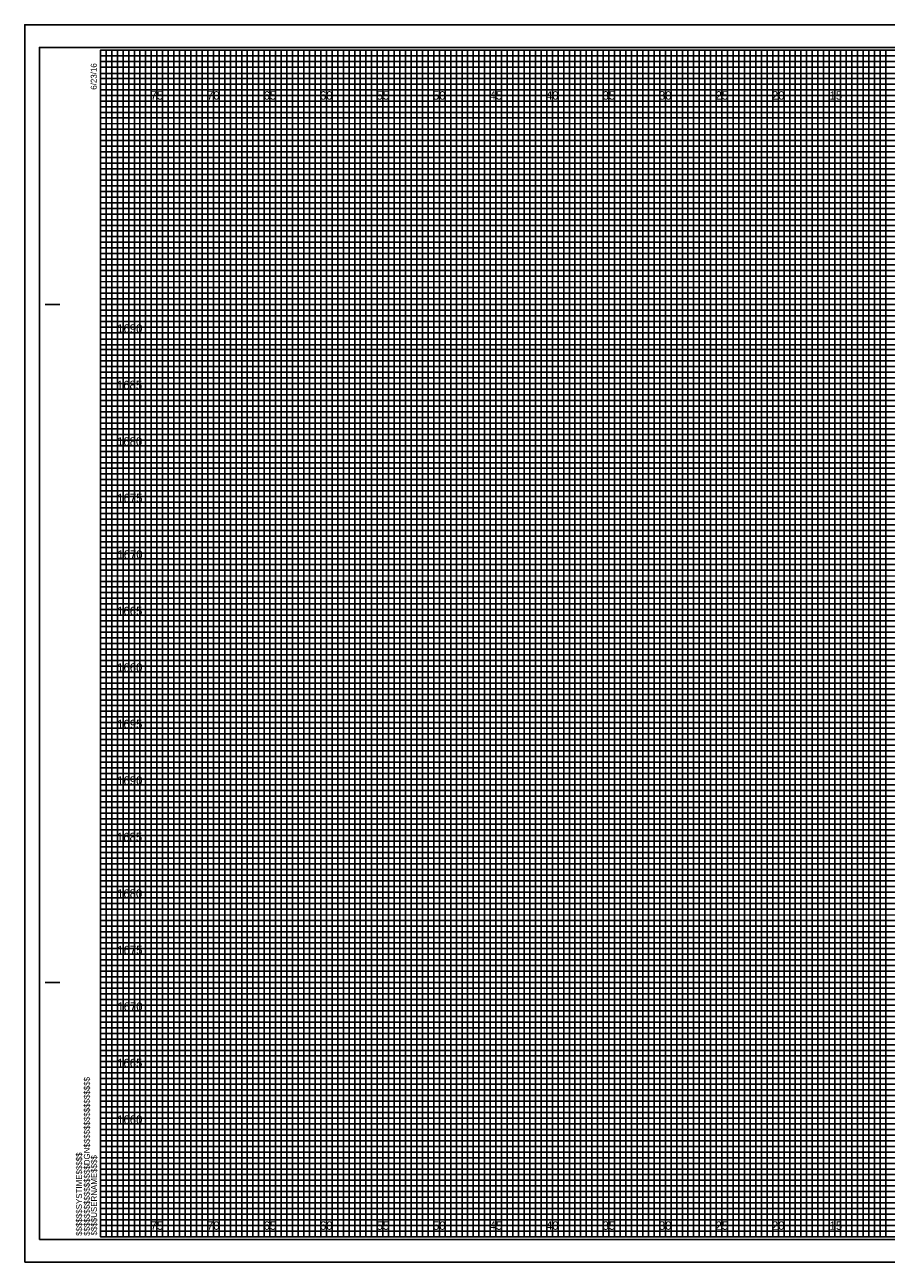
# Model space of a CAD drawing. Extents: x -7 to 162, y -2 to 327.
# Drawn here: x -6.7 to 69.5, y 107.7 to 217.2 of the extents above; entities that cross this region are included whole.
import ezdxf

# ---------------------------------------------------------------- set-up
doc = ezdxf.new("R2010")
doc.units = 0
for name, color, linetype in [('Raster_Level_0', 7, 'Continuous'), ('Scratch_Level_3', 7, 'Continuous'), ('Sheet Cross Section CELL', 7, 'Continuous'), ('Sheet Cross Section Grid Major CELL', 7, 'Continuous'), ('Sheet Cross Section Grid Middle CELL', 7, 'Continuous'), ('Sheet Cross Section Grid Minor 1 CELL', 7, 'Continuous'), ('Sheet Cross Section Grid Minor 2 CELL', 7, 'Continuous'), ('Sheet Cutting Line CELL', 7, 'Continuous'), ('Sheet DOT Grid CELL', 7, 'Continuous'), ('Sheet Plot Border Inside CELL', 7, 'Continuous'), ('Sheet Plot Border Outside CELL', 7, 'Continuous')]:
    doc.layers.add(name, color=color, linetype=linetype)

msp = doc.modelspace()

# ---------------------------------------------------------------- linework, layer by layer
at = {"layer": 'Sheet Cross Section CELL'}
for p, q in [((-4.9, 192.5), (-3.65, 192.5)), ((-4.85, 192.5), (-3.6, 192.5)), ((-4.9, 132.5), (-3.65, 132.5)), ((-4.85, 132.5), (-3.6, 132.5)), ((0, 110), (0, 110)), ((0, 110), (0, 110)), ((0, 110), (0, 110)), ((0, 110), (0, 110)), ((0, 110), (0, 110)), ((0, 110), (0, 110)), ((0, 110), (0, 110))]:
    msp.add_line(p, q, dxfattribs=at)
msp.add_lwpolyline([(160, 215), (0, 215), (0, 110), (160, 110)], close=True, dxfattribs=at)
at = {"layer": 'Sheet Cross Section Grid Major CELL'}
for p, q in [((5, 215), (0, 215)), ((5, 110), (5, 215)), ((15, 215), (10, 215)), ((10, 215), (10, 110)), ((15, 110), (15, 215)), ((25, 215), (20, 215)), ((20, 215), (20, 110)), ((25, 110), (25, 215)), ((35, 215), (30, 215)), ((30, 215), (30, 110)), ((35, 110), (35, 215)), ((45, 215), (40, 215)), ((40, 215), (40, 110)), ((45, 110), (45, 215)), ((55, 215), (50, 215)), ((50, 215), (50, 110)), ((55, 110), (55, 215)), ((65, 215), (60, 215)), ((60, 215), (60, 110)), ((65, 110), (65, 215)), ((10, 110), (5, 110)), ((20, 110), (15, 110)), ((30, 110), (25, 110)), ((40, 110), (35, 110)), ((50, 110), (45, 110)), ((60, 110), (55, 110)), ((70, 110), (65, 110))]:
    msp.add_line(p, q, dxfattribs=at)
for points in [[(0, 210), (160, 210), (160, 205), (0, 205)], [(0, 200), (160, 200), (160, 195), (0, 195)], [(0, 190), (160, 190), (160, 185), (0, 185)], [(0, 180), (160, 180), (160, 175), (0, 175)], [(0, 170), (160, 170), (160, 165), (0, 165)], [(0, 160), (160, 160), (160, 155), (0, 155)], [(0, 150), (160, 150), (160, 145), (0, 145)], [(0, 140), (160, 140), (160, 135), (0, 135)], [(0, 130), (160, 130), (160, 125), (0, 125)], [(0, 120), (160, 120), (160, 115), (0, 115)]]:
    msp.add_lwpolyline(points, dxfattribs=at)
at = {"layer": 'Sheet Cross Section Grid Middle CELL'}
for points in [[(0, 215), (2.5, 215), (2.5, 110), (7.5, 110), (7.5, 215), (12.5, 215), (12.5, 110), (17.5, 110), (17.5, 215), (22.5, 215), (22.5, 110), (27.5, 110), (27.5, 215), (32.5, 215), (32.5, 110), (37.5, 110), (37.5, 215), (42.5, 215), (42.5, 110), (47.5, 110), (47.5, 215), (52.5, 215), (52.5, 110), (57.5, 110), (57.5, 215), (62.5, 215), (62.5, 110), (67.5, 110), (67.5, 215), (72.5, 215)], [(0, 212.5), (137.5, 212.5)], [(0, 202.5), (160, 202.5), (160, 207.5), (0, 207.5)], [(0, 192.5), (160, 192.5), (160, 197.5), (0, 197.5)], [(0, 182.5), (160, 182.5), (160, 187.5), (0, 187.5)], [(0, 172.5), (160, 172.5), (160, 177.5), (0, 177.5)], [(0, 162.5), (160, 162.5), (160, 167.5), (0, 167.5)], [(0, 152.5), (160, 152.5), (160, 157.5), (0, 157.5)], [(0, 142.5), (160, 142.5), (160, 147.5), (0, 147.5)], [(0, 132.5), (160, 132.5), (160, 137.5), (0, 137.5)], [(0, 122.5), (160, 122.5), (160, 127.5), (0, 127.5)], [(0, 112.5), (160, 112.5), (160, 117.5), (0, 117.5)]]:
    msp.add_lwpolyline(points, dxfattribs=at)
at = {"layer": 'Sheet Cross Section Grid Minor 1 CELL'}
for p, q in [((0, 214.5), (130, 214.5)), ((130, 213.99), (0, 213.99)), ((0, 213.99), (0, 213.5)), ((0, 213.5), (130, 213.5)), ((130, 212.94), (0, 212.94)), ((0, 212.94), (0, 212)), ((0, 212), (160, 212))]:
    msp.add_line(p, q, dxfattribs=at)
for points in [[(0, 211.5), (135, 211.5), (160, 211.5), (160, 211), (0, 211)], [(0, 210.5), (160, 210.5), (160, 209.5), (0, 209.5)], [(0, 209), (160, 209), (160, 208.5), (0, 208.49)], [(0, 208), (160, 208), (160, 207), (0, 207)], [(0, 206.5), (160, 206.5), (160, 206), (0, 206)], [(0, 205.5), (160, 205.5), (160, 204.5), (0, 204.5)], [(0, 204), (160, 204), (160, 203.5), (0, 203.5)], [(0, 203), (160, 203), (160, 202), (0, 202)], [(0, 201.5), (160, 201.5), (160, 201), (0, 201)], [(0, 200.5), (160, 200.5), (160, 199.5), (0, 199.5)], [(0, 199), (160, 199), (160, 198.5), (0, 198.5)], [(0, 198), (160, 198), (160, 196.97), (160, 196.5), (160, 196), (0, 196)], [(0, 197), (160, 197), (160, 196.5), (0, 196.5)], [(0, 195.5), (160, 195.5), (160, 194.5), (0, 194.52)], [(0, 194.52), (160, 194.5), (160, 194), (0, 194)], [(0, 193.5), (160, 193.5), (160, 193), (0, 193)], [(0, 192), (160, 192), (160, 191.5), (0, 191.5)], [(0, 191), (160, 191), (160, 190.5), (0, 190.5)], [(-0.04, 189.44), (160, 189.44), (160, 188.94), (-0.04, 188.94)], [(0, 188.5), (160, 188.5), (160, 188), (0, 188)], [(0, 187), (160, 187), (160, 186.5), (0, 186.5)], [(0, 186), (160, 186), (160, 185.5), (0, 185.5)], [(0, 184.5), (160, 184.5), (160, 184), (0, 184)], [(0, 183.5), (160, 183.5), (160, 183), (0, 183)], [(0, 182), (160, 182), (160, 181.5), (0, 181.5)], [(0, 181), (160, 181), (160, 180.5), (0, 180.5)], [(0, 179.5), (160, 179.5), (160, 178.99), (0, 179)], [(0, 178.5), (160, 178.5), (160, 178), (0, 178)], [(0, 177), (160, 177), (160, 176.5), (0, 176.5)], [(0, 176), (160, 176), (160, 175.5), (0, 175.5)], [(0, 174.5), (160, 174.5), (160, 174), (0, 174)], [(0, 173.5), (160, 173.5), (160, 173), (0, 173)], [(0, 172), (160, 172), (160, 171.5), (0, 171.5)], [(0, 171), (160, 171), (160, 170.5), (0, 170.5)], [(0, 169.5), (160, 169.5), (160, 169), (0, 169)], [(0, 168.5), (160.03, 168.46), (160, 168), (0, 168)], [(0, 167), (160, 167), (160, 166.5), (0, 166.5)], [(0, 166), (160, 166), (160, 165.5), (0, 165.5)], [(0, 164.5), (160, 164.5), (160, 164), (0, 164)], [(0, 163.5), (160, 163.5), (160, 163), (0, 163)], [(0, 162), (160, 162), (160, 161.5), (0, 161.5)], [(0, 161), (160, 161), (160, 160.5), (0, 160.5)], [(0, 159.5), (160, 159.5), (160, 159), (0, 159)], [(0, 158.5), (160, 158.5), (160, 158), (0, 158)], [(0, 157), (160, 157), (160, 156.5), (0, 156.5)], [(0, 156), (160, 156), (160, 155.5), (0, 155.5)], [(0, 154.5), (160, 154.5), (160, 154), (0, 154)], [(0, 153.5), (160, 153.5), (160, 153), (0, 153)], [(0, 152), (160, 152), (160, 151.5), (0, 151.5)], [(0, 151), (160, 151), (160, 150.5), (0, 150.5)], [(0, 149.5), (160, 149.5), (160, 148.99), (0, 149)], [(0, 148.5), (160, 148.5), (160, 148), (0, 148)], [(0, 147), (160, 147), (160, 146.5), (0, 146.5)], [(0, 146), (160, 146), (160, 145.5), (0, 145.5)], [(0, 144.5), (160, 144.5), (160, 144), (0, 144)], [(0, 143.5), (160, 143.5), (160, 143), (0, 143)], [(0, 142), (160, 142), (160, 141.5), (0, 141.5)], [(0, 141), (160, 141), (160, 140.5), (0, 140.5)], [(0, 139.5), (160, 139.5), (160, 139), (0, 139)], [(0, 138.5), (160.03, 138.46), (160, 138), (0, 138)], [(0, 137), (160, 137), (160, 136.5), (0, 136.5)], [(0, 136), (160, 136), (160, 135.5), (0, 135.5)], [(0, 134.5), (160, 134.5), (160, 134), (0, 134)], [(0, 133.5), (160, 133.5), (160, 133), (0, 133)], [(0, 132), (160, 132), (160, 131.5), (0, 131.5)], [(0, 131), (160, 131), (160, 130.5), (0, 130.5)], [(0, 129.5), (160, 129.5), (160, 129), (0, 129)], [(0, 128.5), (160, 128.5), (160, 128), (0, 128)], [(0, 127), (160, 127), (160, 126.5), (0, 126.5)], [(0, 126), (160, 126), (160, 125.5), (0, 125.5)], [(0, 124.5), (160, 124.5), (160, 124), (0, 124)], [(0, 123.5), (160, 123.5), (160, 123), (0, 123)], [(0, 122), (160, 122), (160, 121.5), (0, 121.5)], [(0, 121), (160, 121), (160, 120.5), (0, 120.5)], [(0, 119.5), (160, 119.5), (160, 119), (0, 119)], [(0, 118.5), (160, 118.5), (160, 118), (0, 118)], [(0, 117), (160, 117), (160, 116.5), (0, 116.5)], [(0, 116), (160, 116), (160, 115.5), (0, 115.5)], [(0, 114.5), (160, 114.5), (160, 114), (0, 114)], [(0, 113.5), (160, 113.5), (160, 113), (0, 113)], [(0, 112), (160, 112), (160, 111.5), (0, 111.5)], [(0, 111), (160, 111), (160, 110.5), (0, 110.5)]]:
    msp.add_lwpolyline(points, dxfattribs=at)
at = {"layer": 'Sheet Cross Section Grid Minor 2 CELL'}
for points in [[(0, 110), (0.5, 110), (0.5, 215), (1, 215), (1, 110)], [(1, 110), (1.5, 110), (1.5, 215), (2, 215), (2, 110)], [(2.5, 110), (3, 110), (3, 215), (3.5, 215), (3.5, 110)], [(3.5, 110), (4, 110), (4, 215), (4.5, 215), (4.5, 110)], [(5, 110), (5.5, 110), (5.5, 215), (6, 215), (6, 110)], [(6, 110), (6.5, 110), (6.5, 215), (7, 215), (7, 110)], [(7.5, 110), (8, 110), (8, 215), (8.5, 215), (8.5, 110)], [(8.5, 110), (9, 110), (9, 215), (9.5, 215), (9.5, 110)], [(10, 110), (10.5, 110), (10.5, 215), (11, 215), (11, 110)], [(11, 110), (11.5, 110), (11.5, 215), (12, 215), (12, 110)], [(12.5, 110), (13, 110), (13, 215), (13.5, 215), (13.5, 110)], [(13.5, 110), (14, 110), (14, 215), (14.5, 215), (14.5, 110)], [(15, 110), (15.5, 110), (15.5, 215), (16, 215), (16, 110)], [(16, 110), (16.5, 110), (16.5, 215), (17, 215), (17, 110)], [(17.5, 110), (18, 110), (18, 215), (18.5, 215), (18.5, 110)], [(18.5, 110), (19, 110), (19, 215), (19.5, 215), (19.5, 110)], [(20, 110), (20.5, 110), (20.5, 215), (21, 215), (21, 110)], [(21, 110), (21.5, 110), (21.5, 215), (22, 215), (22, 110)], [(22.5, 110), (23, 110), (23, 215), (23.5, 215), (23.5, 110)], [(23.5, 110), (24, 110), (24, 215), (24.5, 215), (24.5, 110)], [(25, 110), (25.5, 110), (25.5, 215), (26, 215), (26, 110)], [(26, 110), (26.5, 110), (26.5, 215), (27, 215), (27, 110)], [(27.5, 110), (28, 110), (28, 215), (28.5, 215), (28.5, 110)], [(28.5, 110), (29, 110), (29, 215), (29.5, 215), (29.5, 110)], [(30, 110), (30.5, 110), (30.5, 215), (31, 215), (31, 110)], [(31, 110), (31.5, 110), (31.5, 215), (32, 215), (32, 110)], [(32.5, 110), (33, 110), (33, 215), (33.5, 215), (33.5, 110)], [(33.5, 110), (34, 110), (34, 215), (34.5, 215), (34.5, 110)], [(35, 110), (35.5, 110), (35.5, 215), (36, 215), (36, 110)], [(36, 110), (36.5, 110), (36.5, 215), (37, 215), (37, 110)], [(37.5, 110), (38, 110), (38, 215), (38.5, 215), (38.5, 110)], [(38.5, 110), (39, 110), (39, 215), (39.5, 215), (39.5, 110)], [(40, 110), (40.5, 110), (40.5, 215), (41, 215), (41, 110)], [(41, 110), (41.5, 110), (41.5, 215), (42, 215), (42, 110)], [(42.5, 110), (43, 110), (43, 215), (43.5, 215), (43.5, 110)], [(43.5, 110), (44, 110), (44, 215), (44.5, 215), (44.5, 110)], [(45, 110), (45.5, 110), (45.5, 215), (46, 215), (46, 110)], [(46, 110), (46.5, 110), (46.5, 215), (47, 215), (47, 110)], [(47.5, 110), (48, 110), (48, 215), (48.5, 215), (48.5, 110)], [(48.5, 110), (49, 110), (49, 215), (49.5, 215), (49.5, 110)], [(50, 110), (50.5, 110), (50.5, 215), (51, 215), (51, 110)], [(51, 110), (51.5, 110), (51.5, 215), (52, 215), (52, 110)], [(52.5, 110), (53, 110), (53, 215), (53.5, 215), (53.5, 110)], [(53.5, 110), (54, 110), (54, 215), (54.5, 215), (54.5, 110)], [(55, 110), (55.5, 110), (55.5, 215), (56, 215), (56, 110)], [(56, 110), (56.5, 110), (56.5, 215), (57, 215), (57, 110)], [(57.5, 110), (58, 110), (58, 215), (58.5, 215), (58.5, 110)], [(58.5, 110), (59, 110), (59, 215), (59.5, 215), (59.5, 110)], [(60, 110), (60.5, 110), (60.5, 215), (61, 215), (61, 110)], [(61, 110), (61.5, 110), (61.5, 215), (62, 215), (62, 110)], [(62.5, 110), (63, 110), (63, 215), (63.5, 215), (63.5, 110)], [(63.5, 110), (64, 110), (64, 215), (64.5, 215), (64.5, 110)], [(65, 110), (65.5, 110), (65.5, 215), (66, 215), (66, 110)], [(66, 110), (66.5, 110), (66.5, 215), (67, 215), (67, 110)], [(67.5, 110), (68, 110), (68, 215), (68.5, 215), (68.5, 110)], [(68.5, 110), (69, 110), (69, 215), (69.5, 215), (69.5, 110)]]:
    msp.add_lwpolyline(points, dxfattribs=at)
at = {"layer": 'Sheet Cutting Line CELL'}
for p, q in [((161.65, 217.25), (-6.7, 217.25)), ((-6.7, 217.25), (-6.7, 107.75)), ((-6.7, 107.75), (161.65, 107.75))]:
    msp.add_line(p, q, dxfattribs=at)
at = {"layer": 'Sheet DOT Grid CELL'}
for p, q in [((5, 110), (5, 215)), ((10, 110), (10, 215)), ((15, 110), (15, 215)), ((20, 110), (20, 215)), ((25, 110), (25, 215)), ((30, 110), (30, 215)), ((35, 110), (35, 215)), ((40, 110), (40, 215)), ((45, 110), (45, 215)), ((50, 110), (50, 215)), ((55, 110), (55, 215)), ((60, 110), (60, 215)), ((65, 110), (65, 215)), ((0, 210), (160, 210)), ((0, 205), (160, 205)), ((0, 200), (160, 200)), ((0, 195), (160, 195)), ((0, 190), (160, 190)), ((0, 185), (160, 185)), ((0, 180), (160, 180)), ((0, 175), (160, 175)), ((0, 170), (160, 170)), ((0, 165), (160, 165)), ((0, 160), (160, 160)), ((0, 155), (160, 155)), ((0, 150), (160, 150)), ((0, 145), (160, 145)), ((0, 140), (160, 140)), ((0, 135), (160, 135)), ((0, 130), (160, 130)), ((0, 125), (160, 125)), ((0, 120), (160, 120)), ((0, 115), (160, 115))]:
    msp.add_line(p, q, dxfattribs=at)
at = {"layer": 'Sheet Plot Border Inside CELL'}
msp.add_lwpolyline([(-5.4, 109.75), (161.2, 109.75), (161.2, 215.25), (-5.4, 215.25)], close=True, dxfattribs=at)
at = {"layer": 'Sheet Plot Border Outside CELL'}
msp.add_lwpolyline([(-6.7, 107.75), (161.65, 107.75), (161.65, 217.25), (-6.7, 217.25)], close=True, dxfattribs=at)

# ---------------------------------------------------------------- texts
at = {"layer": 'Raster_Level_0'}
for s, p in [('75', (4.44, 210.62)), ('70', (9.43, 210.62)), ('65', (14.44, 210.62)), ('60', (19.43, 210.62)), ('55', (24.44, 210.62)), ('50', (29.43, 210.62)), ('45', (34.44, 210.62)), ('40', (39.43, 210.62)), ('35', (44.44, 210.62)), ('30', (49.43, 210.62)), ('25', (54.44, 210.62)), ('20', (59.43, 210.62)), ('15', (64.53, 210.62)), ('75', (4.44, 110.62)), ('70', (9.43, 110.62)), ('65', (14.44, 110.62)), ('60', (19.43, 110.62)), ('55', (24.44, 110.62)), ('50', (29.43, 110.62)), ('45', (34.44, 110.62)), ('40', (39.43, 110.62)), ('35', (44.44, 110.62)), ('30', (49.43, 110.62)), ('25', (54.44, 110.62)), ('20', (59.43, 110.62)), ('15', (64.53, 110.62))]:
    msp.add_text(s, height=0.75, dxfattribs=at).set_placement(p)
at = {"layer": 'Scratch_Level_3'}
for s, p in [('1690', (1.48, 190)), ('1685', (1.46, 185)), ('1680', (1.47, 180)), ('1675', (1.49, 175)), ('1670', (1.5, 170)), ('1665', (1.48, 165)), ('1660', (1.48, 160)), ('1695', (1.48, 155)), ('1690', (1.48, 150)), ('1685', (1.46, 145)), ('1680', (1.47, 140)), ('1675', (1.49, 135)), ('1670', (1.5, 130)), ('1665', (1.48, 125)), ('1660', (1.48, 120))]:
    msp.add_text(s, height=0.75, dxfattribs=at).set_placement(p)
at = {"layer": 'Sheet Cross Section CELL'}
for s, p in [('6/23/16', (-0.33, 211.5)), ('$$$$$$$$$$$$$$$$DGN$$$$$$$$$$$$$$$$', (-0.94, 110.09)), ('$$$$$$SYSTIME$$$$$', (-1.63, 110.09)), ('$$$$USERNAME$$$$', (-0.31, 110.12))]:
    msp.add_text(s, height=0.525, rotation=90, dxfattribs=at).set_placement(p)

doc.saveas('drawing.dxf')
